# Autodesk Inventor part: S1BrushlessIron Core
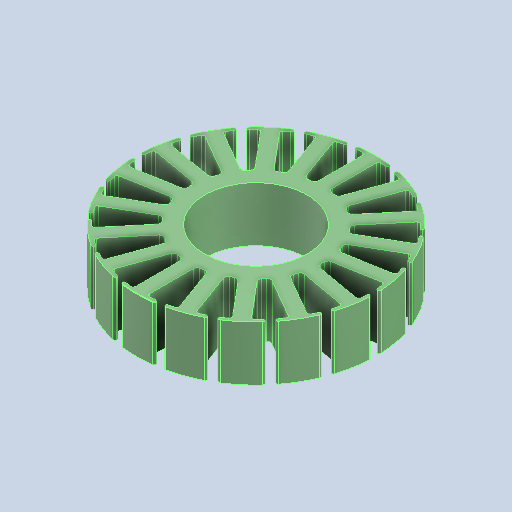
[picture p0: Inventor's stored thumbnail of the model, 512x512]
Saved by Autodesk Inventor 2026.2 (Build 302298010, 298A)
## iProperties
Created: 1601-01
Part Number: S1BrushlessIron Core
Material: Ductile Iron
Document SubType Name: Modeling
Designer: mel
Density: 7.1 g/cm^3
Appearance: 0,128,0
Author: mel
Sending System: SOLIDWORKS 2023
Part Number: Iron Core
Last Saved Date: 2025-04-02
last saved by: pierr
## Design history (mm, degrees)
fillet "Fillet3"
node "Axis1"
node "Solide1"
